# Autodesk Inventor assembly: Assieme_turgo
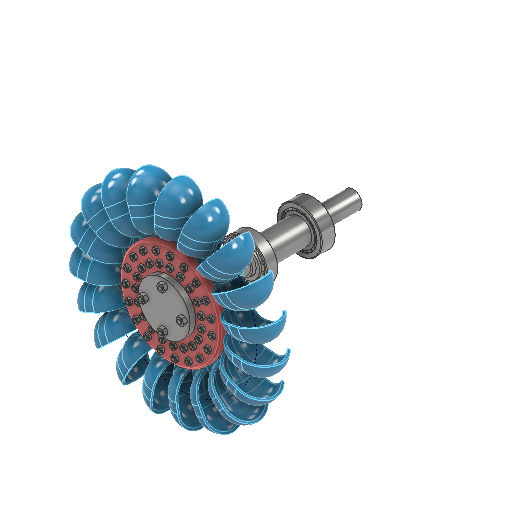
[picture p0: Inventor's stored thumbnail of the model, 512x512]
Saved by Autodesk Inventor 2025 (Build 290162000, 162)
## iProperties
Created: 2025-03
Part Number: Assieme_turgo
Document SubType Name: Assembly
Designer: R5800u
Author: R5800u
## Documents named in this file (13)
- C:\Users\R5800u\Desktop\turgo\Assieme_turgo.iam
- C:\Users\R5800u\Desktop\turgo\Parte2.ipt
- C:\Users\R5800u\Desktop\turgo\Parte1.ipt
- C:\Users\R5800u\Desktop\turgo\disco.ipt
- C:\Users\R5800u\Desktop\turgo\disco_MIR.ipt
- C:\Users\R5800u\Documents\Inventor\Content Center Files\R2025\it-IT\AS 1111\AS 1111 - M5 x 30.ipt
- C:\Users\R5800u\Documents\Inventor\Content Center Files\R2025\it-IT\AS 1112 (4)\AS 1112 - M5(2).ipt
- C:\Users\R5800u\Desktop\turgo\Assieme_turgo\Design Accelerator\Connessione a chiavetta2.iam
- C:\Users\R5800u\Desktop\turgo\albero.ipt
- C:\Users\R5800u\Documents\Inventor\Content Center Files\R2025\it-IT\AS 1110\AS 1110 - M6 x 40.ipt
- C:\Users\R5800u\Documents\Inventor\Content Center Files\R2025\it-IT\AS 1112 (2)\AS 1112 - M6  Tipo 5.ipt
- C:\Users\R5800u\Documents\Inventor\Content Center Files\R2025\it-IT\SKF - with Tapered Bore\SKF22206 CCK.ipt
- C:\Users\R5800u\Documents\Inventor\Content Center Files\R2025\it-IT\JIS B 1533 SKF (A)\JIS B 1533 SKF (A) - SKF N 206 ECP.ipt
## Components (110 placed, 12 different names)
1. Parte2:1
2. disco:1 — Allineato:3, Coincidente:3, Rotazionale:1
3. disco_MIR:1
4. AS 1111 - Metrico M5 x 30:1
5. AS 1111 - Metrico M5 x 30:2
6. AS 1111 - Metrico M5 x 30:3
7. AS 1111 - Metrico M5 x 30:4
8. AS 1111 - Metrico M5 x 30:5
9. AS 1111 - Metrico M5 x 30:6
10. AS 1111 - Metrico M5 x 30:7
11. AS 1111 - Metrico M5 x 30:8
12. AS 1111 - Metrico M5 x 30:9
13. AS 1111 - Metrico M5 x 30:10
14. AS 1111 - Metrico M5 x 30:11
15. AS 1111 - Metrico M5 x 30:12
16. AS 1111 - Metrico M5 x 30:13
17. AS 1111 - Metrico M5 x 30:14
18. AS 1111 - Metrico M5 x 30:15
19. AS 1111 - Metrico M5 x 30:16
20. AS 1111 - Metrico M5 x 30:17
21. AS 1111 - Metrico M5 x 30:18
22. AS 1111 - Metrico M5 x 30:19
23. AS 1111 - Metrico M5 x 30:20
24. AS 1111 - Metrico M5 x 30:21
25. AS 1111 - Metrico M5 x 30:22
26. AS 1111 - Metrico M5 x 30:23
27. AS 1111 - Metrico M5 x 30:24
28. AS 1111 - Metrico M5 x 30:25
29. AS 1111 - Metrico M5 x 30:26
30. AS 1111 - Metrico M5 x 30:27
31. AS 1111 - Metrico M5 x 30:28
32. AS 1111 - Metrico M5 x 30:29
33. AS 1111 - Metrico M5 x 30:30
34. AS 1111 - Metrico M5 x 30:31
35. AS 1111 - Metrico M5 x 30:32
36. AS 1111 - Metrico M5 x 30:33
37. AS 1111 - Metrico M5 x 30:34
38. AS 1111 - Metrico M5 x 30:35
39. AS 1111 - Metrico M5 x 30:36
40. AS 1111 - Metrico M5 x 30:37
41. AS 1111 - Metrico M5 x 30:38
42. AS 1112 (4) - Metrico M5:1 — Coincidente:3
43. AS 1112 (4) - Metrico M5:2
44. AS 1112 (4) - Metrico M5:3
45. AS 1112 (4) - Metrico M5:4
46. AS 1112 (4) - Metrico M5:5
47. AS 1112 (4) - Metrico M5:6
48. AS 1112 (4) - Metrico M5:7
49. AS 1112 (4) - Metrico M5:8
50. AS 1112 (4) - Metrico M5:9
51. AS 1112 (4) - Metrico M5:10
52. AS 1112 (4) - Metrico M5:11
53. AS 1112 (4) - Metrico M5:12
54. AS 1112 (4) - Metrico M5:13
55. AS 1112 (4) - Metrico M5:14
56. AS 1112 (4) - Metrico M5:15
57. AS 1112 (4) - Metrico M5:16
58. AS 1112 (4) - Metrico M5:17
59. AS 1112 (4) - Metrico M5:18
60. AS 1112 (4) - Metrico M5:19
61. AS 1112 (4) - Metrico M5:20
62. AS 1112 (4) - Metrico M5:21
63. AS 1112 (4) - Metrico M5:22
64. AS 1112 (4) - Metrico M5:23
65. AS 1112 (4) - Metrico M5:24
66. AS 1112 (4) - Metrico M5:25
67. AS 1112 (4) - Metrico M5:26
68. AS 1112 (4) - Metrico M5:27
69. AS 1112 (4) - Metrico M5:28
70. AS 1112 (4) - Metrico M5:29
71. AS 1112 (4) - Metrico M5:30
72. AS 1112 (4) - Metrico M5:31
73. AS 1112 (4) - Metrico M5:32
74. AS 1112 (4) - Metrico M5:33
75. AS 1112 (4) - Metrico M5:34
76. AS 1112 (4) - Metrico M5:36
77. AS 1112 (4) - Metrico M5:37
78. AS 1112 (4) - Metrico M5:38
79. AS 1112 (4) - Metrico M5:39
80. Connessione a chiavetta:1 [sub-assembly]
81. albero:1
82. AS 1110 - Metrico M6 x 40:1 — Coincidente:5
83. AS 1110 - Metrico M6 x 40:2 — Coincidente:7
84. AS 1110 - Metrico M6 x 40:3 — Coincidente:9
85. AS 1110 - Metrico M6 x 40:4 — Coincidente:11
86. AS 1112 (2) - Metrico M6  Tipo 5:1 — Coincidente:13
87. AS 1112 (2) - Metrico M6  Tipo 5:2 — Coincidente:15
88. AS 1112 (2) - Metrico M6  Tipo 5:3 — Coincidente:17
89. AS 1112 (2) - Metrico M6  Tipo 5:4 — Coincidente:19
90. SKF- con foro rastremato SKF22206 CCK:1 — Coincidente:21
91. JIS B 1533 SKF- tipo N SKF N 206 ECP:1 — Coincidente:23
92. Parte1:1 — Allineato:1, Coincidente:1, Allineato:2
93. Parte1:2
94. Parte1:3
95. Parte1:4
96. Parte1:5
97. Parte1:6
98. Parte1:7
99. Parte1:8
100. Parte1:9
101. Parte1:10
102. Parte1:11
103. Parte1:12
104. Parte1:13
105. Parte1:14
106. Parte1:15
107. Parte1:16
108. Parte1:17
109. Parte1:18
110. Parte1:19
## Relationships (16: Mate 12, Flush 3, RevoluteJoint 1)
- Allineato:1 [Flush]: Parte1:1
- Coincidente:1 [Mate]: Parte1:1
- Allineato:2 [Flush]: Parte1:1
- Allineato:3 [Flush]: disco:1
- Coincidente:3 [Mate]: disco:1 ↔ AS 1112 (4) - Metrico M5:1
- Rotazionale:1 [RevoluteJoint]: disco:1
- Coincidente:5 [Mate]: AS 1110 - Metrico M6 x 40:1
- Coincidente:7 [Mate]: AS 1110 - Metrico M6 x 40:2
- Coincidente:9 [Mate]: AS 1110 - Metrico M6 x 40:3
- Coincidente:11 [Mate]: AS 1110 - Metrico M6 x 40:4
- Coincidente:13 [Mate]: AS 1112 (2) - Metrico M6  Tipo 5:1
- Coincidente:15 [Mate]: AS 1112 (2) - Metrico M6  Tipo 5:2
- Coincidente:17 [Mate]: AS 1112 (2) - Metrico M6  Tipo 5:3
- Coincidente:19 [Mate]: AS 1112 (2) - Metrico M6  Tipo 5:4
- Coincidente:21 [Mate]: SKF- con foro rastremato SKF22206 CCK:1
- Coincidente:23 [Mate]: JIS B 1533 SKF- tipo N SKF N 206 ECP:1
